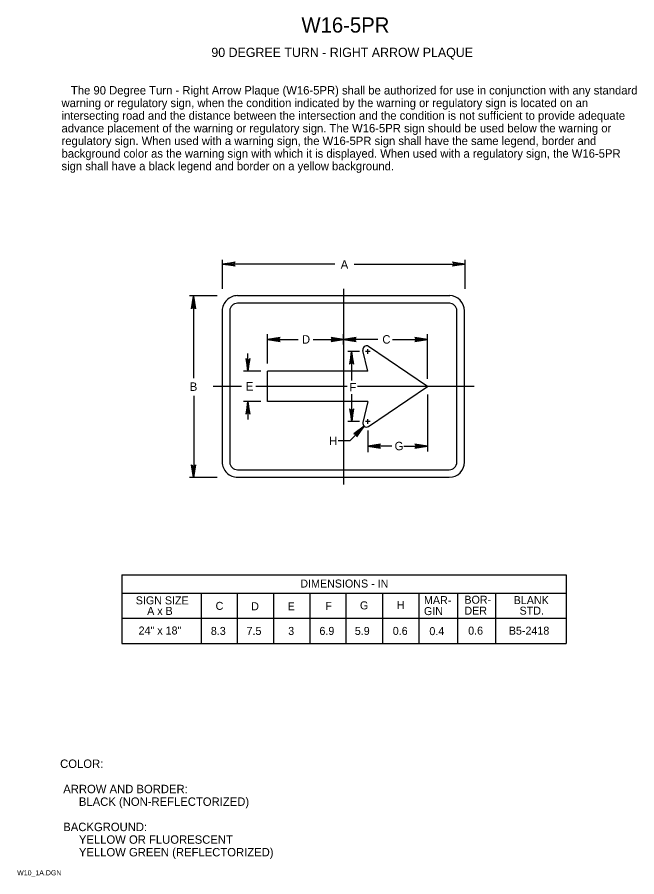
# Model space of a CAD drawing. Extents: x 0.013 to 0.197, y 0.004 to 0.259.
import ezdxf

# ---------------------------------------------------------------- set-up
doc = ezdxf.new("R2010")
doc.units = 0
for name, color, linetype in [('1', 7, 'Continuous'), ('2', 7, 'Continuous'), ('3', 7, 'Continuous')]:
    doc.layers.add(name, color=color, linetype=linetype)

# ---------------------------------------------------------------- blocks, each defined once
blk = doc.blocks.new('RARROW')
at = {"layer": '3'}
for p, q in [((-2.156, 0.28500000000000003), (-2.2665, 0.384625)), ((-2.2665, 0.384625), (0, 0)), ((0, 0), (-2.2665, -0.379125)), ((-2.156, 0.28500000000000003), (-2.075625, 0.12075)), ((0, 0), (-2.156, 0.28500000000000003)), ((-2.14975, -0.2705), (0, 0)), ((-2.075625, 0.12075), (0, 0)), ((0, 0), (-2.074, -0.108)), ((-2.2665, -0.379125), (-2.14975, -0.2705)), ((-2.074, -0.108), (-2.14975, -0.2705))]:
    blk.add_line(p, q, dxfattribs=at)

msp = doc.modelspace()

# ---------------------------------------------------------------- linework, layer by layer
at = {"layer": '1'}
for p, q in [((0.10950948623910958, 0.1784793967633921), (0.10950948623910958, 0.1204219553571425)), ((0.11667221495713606, 0.15397023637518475), (0.08693448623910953, 0.15397023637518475)), ((0.07919588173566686, 0.14947023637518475), (0.0708303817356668, 0.14947023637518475)), ((0.0837022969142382, 0.14947023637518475), (0.08340352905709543, 0.14947023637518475)), ((0.1105364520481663, 0.14947023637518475), (0.0837022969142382, 0.14947023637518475)), ((0.1482268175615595, 0.14947023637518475), (0.11363359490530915, 0.14947023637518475)), ((0.11667221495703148, 0.14497023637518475), (0.08693448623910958, 0.14497023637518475))]:
    msp.add_line(p, q, dxfattribs=at)
at = {"layer": '3'}
for p, q in [((0.07359843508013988, 0.17841642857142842), (0.07359843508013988, 0.18703855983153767)), ((0.1455984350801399, 0.17841642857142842), (0.1455984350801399, 0.18703855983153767)), ((0.10689328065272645, 0.18578855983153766), (0.07363359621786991, 0.18578855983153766)), ((0.1125947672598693, 0.18578855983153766), (0.1455984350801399, 0.18578855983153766)), ((0.07196701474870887, 0.17641355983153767), (0.0637585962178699, 0.17641355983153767)), ((0.0650085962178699, 0.1519761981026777), (0.0650085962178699, 0.17641355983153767)), ((0.14105197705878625, 0.17641642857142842), (0.07796701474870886, 0.17641642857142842)), ((0.14099731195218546, 0.17416642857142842), (0.07796701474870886, 0.17416642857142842)), ((0.07346701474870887, 0.17191642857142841), (0.07346701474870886, 0.12701630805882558)), ((0.07571701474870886, 0.17191642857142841), (0.07571701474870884, 0.1270163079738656)), ((0.14311543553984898, 0.12702017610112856), (0.14311543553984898, 0.171920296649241)), ((0.14536543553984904, 0.12702017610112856), (0.145365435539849, 0.171920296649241)), ((0.08693448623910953, 0.15633322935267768), (0.08693448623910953, 0.16495536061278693)), ((0.08693448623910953, 0.16340406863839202), (0.09596733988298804, 0.16340406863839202)), ((0.1004737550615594, 0.16340406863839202), (0.10950948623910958, 0.16340406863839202)), ((0.11961979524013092, 0.16340406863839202), (0.10950948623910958, 0.16340406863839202)), ((0.10951148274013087, 0.1619188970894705), (0.10951148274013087, 0.16495536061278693)), ((0.12402662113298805, 0.16340406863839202), (0.13436834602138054, 0.16340406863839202)), ((0.13436834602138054, 0.15176078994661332), (0.13436834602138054, 0.16495536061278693)), ((0.13436834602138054, 0.14947023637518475), (0.11685409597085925, 0.16137481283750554)), ((0.08110363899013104, 0.1539742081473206), (0.08110363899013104, 0.15928200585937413)), ((0.1142086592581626, 0.1598577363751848), (0.11076660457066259, 0.1598577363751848)), ((0.11189221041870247, 0.15126902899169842), (0.11189221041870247, 0.15904849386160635)), ((0.11667221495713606, 0.15397023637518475), (0.11524005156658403, 0.16017724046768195)), ((0.11668502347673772, 0.1598577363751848), (0.11596790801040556, 0.1598577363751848)), ((0.11668502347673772, 0.1598577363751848), (0.11668502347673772, 0.16057485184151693)), ((0.11668502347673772, 0.15914062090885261), (0.11668502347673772, 0.1598577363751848)), ((0.11740213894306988, 0.1598577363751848), (0.11668502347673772, 0.1598577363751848)), ((0.0849129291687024, 0.15397023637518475), (0.07975918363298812, 0.15397023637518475)), ((0.08693448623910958, 0.14497023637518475), (0.08693448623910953, 0.15397023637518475)), ((0.11685105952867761, 0.13755506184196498), (0.13436834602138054, 0.14947023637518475)), ((0.0650085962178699, 0.14667306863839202), (0.0650085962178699, 0.12258255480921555)), ((0.11189221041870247, 0.13909420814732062), (0.11189221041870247, 0.14722331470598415)), ((0.13436834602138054, 0.14704617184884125), (0.13436834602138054, 0.1301261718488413)), ((0.0849129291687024, 0.14497023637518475), (0.07975918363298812, 0.14497023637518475)), ((0.08110363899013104, 0.14497023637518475), (0.08110363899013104, 0.13966243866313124)), ((0.11667221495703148, 0.14497023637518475), (0.11524005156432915, 0.13876323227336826)), ((0.11420943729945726, 0.13908273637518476), (0.11076738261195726, 0.13908273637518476)), ((0.11668502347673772, 0.13908273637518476), (0.11596790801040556, 0.13908273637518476)), ((0.11668502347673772, 0.13908273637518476), (0.11668502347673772, 0.13979985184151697)), ((0.11668502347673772, 0.13836562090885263), (0.11668502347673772, 0.13908273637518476)), ((0.11740213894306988, 0.13908273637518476), (0.11668502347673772, 0.13908273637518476)), ((0.11556658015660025, 0.13766902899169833), (0.11130769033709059, 0.13333585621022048)), ((0.11668502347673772, 0.1363890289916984), (0.11668502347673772, 0.12998902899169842)), ((0.11130769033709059, 0.13333585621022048), (0.10786563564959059, 0.13333585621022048)), ((0.1237951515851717, 0.13175474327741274), (0.11665515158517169, 0.13175474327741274)), ((0.12734943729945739, 0.13175474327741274), (0.13436834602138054, 0.13175474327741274)), ((0.07796701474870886, 0.12476630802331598), (0.14086543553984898, 0.12476630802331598)), ((0.07796701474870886, 0.12251630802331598), (0.14086543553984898, 0.12251630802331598)), ((0.07196701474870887, 0.12241355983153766), (0.0637585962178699, 0.12241355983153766)), ((0.043705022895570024, 0.09354213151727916), (0.17553288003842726, 0.09354213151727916)), ((0.043705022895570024, 0.09354213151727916), (0.043705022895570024, 0.07316713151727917)), ((0.17553288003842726, 0.09354213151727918), (0.17553288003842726, 0.07316713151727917)), ((0.043705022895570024, 0.08816713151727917), (0.17553288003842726, 0.08816713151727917)), ((0.06720502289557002, 0.08816713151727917), (0.06720502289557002, 0.07316713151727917)), ((0.07795502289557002, 0.08816713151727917), (0.07795502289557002, 0.07316713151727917)), ((0.08870502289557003, 0.08816713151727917), (0.08870502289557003, 0.07316713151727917)), ((0.09945502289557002, 0.08816713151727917), (0.09945502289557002, 0.07316713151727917)), ((0.11020502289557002, 0.08816713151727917), (0.11020502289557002, 0.07316713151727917)), ((0.12108002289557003, 0.08816713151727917), (0.12108002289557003, 0.07316713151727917)), ((0.13183002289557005, 0.08816713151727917), (0.13183002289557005, 0.07316713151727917)), ((0.14326428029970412, 0.08816713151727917), (0.14326428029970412, 0.07316713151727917)), ((0.1545968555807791, 0.08816713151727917), (0.1545968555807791, 0.07316713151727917)), ((0.043705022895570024, 0.08066713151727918), (0.17553288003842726, 0.08066713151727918)), ((0.043705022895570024, 0.07316713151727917), (0.17553288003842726, 0.07316713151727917))]:
    msp.add_line(p, q, dxfattribs=at)
for centre, radius, start, end in [((0.07799927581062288, 0.17188803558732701), 0.004532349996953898, 89.64106666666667, 179.6410666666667), ((0.14086543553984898, 0.171920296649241), 0.0045000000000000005, 0, 90), ((0.07799927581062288, 0.17188803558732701), 0.0022824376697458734, 89.28723611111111, 179.2872361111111), ((0.14086543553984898, 0.171920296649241), 0.0022500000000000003, 0, 90), ((0.11630090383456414, 0.160433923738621), 0.0010914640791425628, 59.54676398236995, 193.60184176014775), ((0.11630090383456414, 0.13850654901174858), 0.0010914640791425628, 166.39815823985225, 300.45323601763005), ((0.07799540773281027, 0.12704856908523), 0.004528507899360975, 180.4081777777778, 270.40817777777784), ((0.07799540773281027, 0.12704856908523), 0.002278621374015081, 180.81123055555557, 270.81123055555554), ((0.14086543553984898, 0.12702017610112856), 0.0045000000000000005, 270, 0), ((0.14086543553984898, 0.12702017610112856), 0.0022500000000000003, 270, 0)]:
    msp.add_arc(centre, radius, start, end, dxfattribs=at)

# ---------------------------------------------------------------- block references
for p, xscale, yscale, rotation in [((0.07359201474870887, 0.1857914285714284), 0.0016545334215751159, 0.0016366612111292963, 180), ((0.06496701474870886, 0.1762914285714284), 0.0016545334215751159, 0.0016366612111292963, 90), ((0.08693448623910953, 0.16340406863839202), 0.0016545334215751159, -0.0016366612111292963, 180), ((0.10950948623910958, 0.16340406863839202), 0.0016545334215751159, -0.0016366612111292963, 180), ((0.11187800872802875, 0.15988617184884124), 0.0016545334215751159, -0.0016366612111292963, 90.00000000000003), ((0.08110363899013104, 0.1539742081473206), 0.0016545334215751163, -0.0016366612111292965, -89.99999999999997), ((0.08110363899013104, 0.14497023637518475), 0.0016545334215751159, -0.0016366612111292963, 90.00000000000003), ((0.11189221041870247, 0.13909420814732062), 0.0016545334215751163, -0.0016366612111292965, -89.99999999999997), ((0.11556658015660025, 0.13766902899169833), 0.0016545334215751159, -0.0016366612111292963, 45.49534021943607), ((0.11665515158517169, 0.13175474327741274), 0.0016545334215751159, -0.0016366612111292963, 180), ((0.06496701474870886, 0.1224604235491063), 0.0016545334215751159, 0.0016366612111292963, -90)]:
    msp.add_blockref('RARROW', p, dxfattribs=dict(at, xscale=xscale, yscale=yscale, rotation=rotation))
at = {"layer": '3', "xscale": 0.0016545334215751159}
for p, yscale in [((0.1455984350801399, 0.18578855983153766), 0.0016366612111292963), ((0.10950948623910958, 0.16340406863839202), -0.0016366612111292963), ((0.13436834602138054, 0.16340406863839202), -0.0016366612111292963), ((0.13436834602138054, 0.13175474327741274), -0.0016366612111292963)]:
    msp.add_blockref('RARROW', p, dxfattribs=dict(at, yscale=yscale))

# ---------------------------------------------------------------- texts
at = {"layer": '1'}
for s, height, p in [('W16-5PR', 0.0045000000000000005, (0.09699590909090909, 0.2545)), ('90 DEGREE TURN - RIGHT ARROW PLAQUE', 0.00275025, (0.07025592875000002, 0.24725)), ('COLOR:', 0.0024997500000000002, (0.025375, 0.036249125)), (' ARROW AND BORDER:', 0.0024997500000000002, (0.025375, 0.028749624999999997)), ('      BLACK (NON-REFLECTORIZED)', 0.0024997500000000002, (0.025375, 0.024999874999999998)), (' BACKGROUND:', 0.0024997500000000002, (0.025375, 0.017500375)), ('      YELLOW OR FLUORESCENT ', 0.0024997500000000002, (0.025375, 0.013750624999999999)), ('      YELLOW GREEN (REFLECTORIZED)', 0.0024997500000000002, (0.025375, 0.010000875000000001)), ('W10_1A.DGN', 0.0015, (0.012625, 0.004375))]:
    msp.add_text(s, height=height, dxfattribs=at).set_placement(p)
at = {"layer": '2'}
for s, p in [('   The 90 Degree Turn - Right Arrow Plaque (W16-5PR) shall be authorized for use in conjunction with any standard ', (0.02578829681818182, 0.23612525)), ('warning or regulatory sign, when the condition indicated by the warning or regulatory sign is located on an ', (0.02578829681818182, 0.23237549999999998)), ('intersecting road and the distance between the intersection and the condition is not sufficient to provide adequate ', (0.02578829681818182, 0.22862575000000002)), ('advance placement of the warning or regulatory sign. The W16-5PR sign should be used below the warning or ', (0.02578829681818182, 0.22487600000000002)), ('regulatory sign. When used with a warning sign, the W16-5PR sign shall have the same legend, border and ', (0.02578829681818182, 0.22112625)), ('background color as the warning sign with which it is displayed. When used with a regulatory sign, the W16-5PR ', (0.02578829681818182, 0.2173765)), ('sign shall have a black legend and border on a yellow background.', (0.02578829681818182, 0.21362675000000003))]:
    msp.add_text(s, height=0.0024997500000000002, dxfattribs=at).set_placement(p)
at = {"layer": '3'}
for s, height, p in [('A', 0.0024997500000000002, (0.10864247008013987, 0.18441642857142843)), ('D', 0.0024997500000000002, (0.09714103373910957, 0.1621903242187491)), ('C', 0.0024997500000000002, (0.1210021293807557, 0.1621903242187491)), ('B', 0.0024997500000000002, (0.06384201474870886, 0.14816368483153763)), ('E', 0.0024997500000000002, (0.08047825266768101, 0.14824782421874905)), ('F', 0.0024997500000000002, (0.11123281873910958, 0.14798902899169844)), ('H', 0.0024997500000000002, (0.10520114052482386, 0.13206902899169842)), ('G', 0.0024997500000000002, (0.12464046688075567, 0.13054099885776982)), ('DIMENSIONS - IN', 0.0023752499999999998, (0.09666124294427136, 0.08979213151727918)), ('SIGN SIZE', 0.0023752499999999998, (0.04783002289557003, 0.08479213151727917)), ('MAR-', 0.0023752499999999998, (0.13334707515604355, 0.08486676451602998)), ('BOR-', 0.0023752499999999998, (0.14534707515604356, 0.08499176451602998)), ('BLANK', 0.0023752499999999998, (0.1599720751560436, 0.08486676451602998)), ('C', 0.0023752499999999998, (0.07150814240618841, 0.08316713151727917)), ('D', 0.0023752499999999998, (0.08208002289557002, 0.08304213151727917)), ('E', 0.0023752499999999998, (0.09290002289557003, 0.08304213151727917)), ('F', 0.0023752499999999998, (0.10408002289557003, 0.08316713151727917)), ('G', 0.0023752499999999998, (0.11434288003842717, 0.08330564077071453)), ('H', 0.0023752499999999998, (0.1252581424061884, 0.08339561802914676)), ('A x B', 0.0023752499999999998, (0.051205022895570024, 0.08166713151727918)), ('GIN', 0.0023752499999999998, (0.13334707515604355, 0.08161676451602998)), ('DER', 0.0023752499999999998, (0.14534707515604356, 0.08174176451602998)), ('STD.', 0.0023752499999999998, (0.16172207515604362, 0.08174176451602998)), ('24" x 18"', 0.0023752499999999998, (0.04866636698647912, 0.07585450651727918)), ('8.3', 0.0023752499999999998, (0.07010808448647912, 0.07572950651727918)), ('7.5', 0.0023752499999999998, (0.0807014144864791, 0.07572950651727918)), ('3', 0.0023752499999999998, (0.0930587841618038, 0.07572950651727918)), ('6.9', 0.0023752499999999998, (0.10232713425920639, 0.07572950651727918)), ('5.9', 0.0023752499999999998, (0.11282713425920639, 0.07572950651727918)), ('0.6', 0.0023752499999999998, (0.12408710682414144, 0.07572950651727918)), ('0.4', 0.0023752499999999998, (0.13495407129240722, 0.07567913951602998)), ('0.6', 0.0023752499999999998, (0.14646558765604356, 0.07580413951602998)), ('B5-2418', 0.0023752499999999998, (0.15853243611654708, 0.07580413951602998))]:
    msp.add_text(s, height=height, dxfattribs=at).set_placement(p)

doc.saveas('drawing.dxf')
